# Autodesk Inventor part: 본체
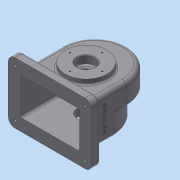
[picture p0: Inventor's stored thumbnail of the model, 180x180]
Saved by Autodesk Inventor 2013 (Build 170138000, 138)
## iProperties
Created: 2017-11
Part Number: 본체
Material: 일반
Document SubType Name: Modeling
Designer: Administrator
Density: 1 g/cm^3
Author: Administrator
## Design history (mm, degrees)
sketch "스케치1"
  geometry: L1 (-58, 0)-(-58, -80); L2 (-58, -80)-(58, -80); L3 (58, 0)-(58, -80); A1 r 58 centre (0, 0) between (58, 0) and (-58, 0); 1 further point
  constraints: 6 end point, 2 perpendicular, 2 point on circle, 2 tangent, 1 centre point, 1 coincident, 1 vertical
  dimensions: "d0" = 116 diameter of A1; "d2" = 80 distance from line of L3.start L2
extrude "돌출1" new body sketch "스케치1" distance "d3" = 38; taper "d4" = 0 deg
sketch "스케치2"
  geometry: L1 (-58, -80)-(58, -80) reference; L2 (58, -80)-(58, 0) reference; L3 (-58, -23)-(-58, -80); L4 (-58, -80)-(58, -80); L5 (58, -23)-(58, -80); A1 r 58 centre (0, 0) between (58, 0) and (-58, 0) reference; A2 r 58 centre (0, -23) between (58, -23) and (-58, -23); 2 further points
  constraints: 6 end point, 2 midpoint, 2 perpendicular, 2 point on circle, 2 tangent, 1 centre point, 1 coincident, 1 parallel, 1 vertical alignment
  dimensions: "d6" = 57 distance from line of L4 L5.start; "d8" = 58 radius of A2
extrude "돌출2" join sketch "스케치2" distance "d9" = 38; taper "d10" = 0 deg
feature "쉘1" dims "d11" = 5
sketch "스케치3"
  geometry: L1 (-58, -80)-(58, -80) reference; C1 r 37.5 at (0, -15); A1 r 58 centre (0, 0) between (58, 0) and (-58, 0) reference
  constraints: 1 centre point, 1 vertical alignment
  dimensions: "d12" = 75 diameter of C1; "d13" = 65 distance from line of L1 C1.centre
extrude "돌출3" join sketch "스케치3" distance "d14" = 9; taper "d15" = 0 deg
sketch "스케치4"
  geometry: L1 (-58, -80)-(58, -80) reference; C1 r 31 at (0, -15); 1 further point
  constraints: 1 centre point, 1 vertical alignment
  dimensions: "d16" = 62 diameter of C1; "d17" = 65 distance from line of L1 C1.centre
extrude "돌출4" join sketch "스케치4" distance "d18" = 10; taper "d19" = 0 deg
sketch "스케치5"
  geometry: C1 r 31 at (0, 0) reference; 1 further point
hole "구멍1" sketch "스케치5" at (0, 0) diameter "d20" = 32; stored, may be unused: countersink angle "d24" = 90 deg, drill point angle "d26" = 118 deg; dims "d21" = 6, "d22" = 4, "d23" = 2, "d25" = 8
chamfer "모따기1" distance "d29" = 1; stored, may be unused: second distance "d30" = 2, angle "d31" = 45 deg
fillet "모깎기2" dims "d32" = 3
fillet "모깎기3" dims "d33" = 3
node "작업 평면1"
sketch "스케치6"
  geometry: L1 (58, 38)-(-58, 38) reference; C1 r 6 at (0, 19); 1 further point
  constraints: 1 centre point, 1 vertical alignment
  dimensions: "d35" = 12 diameter of C1; "d47" = 19 distance from line of L1 C1.centre
extrude "돌출5" join sketch "스케치6" stored distance "d38" = 10; taper "d39" = 0 deg
sketch "스케치7"
  geometry: C1 r 6 at (0, 0) reference; 1 further point
hole "구멍2" sketch "스케치7" at (0, 0) diameter "d40" = 4.459; stored, may be unused: countersink angle "d44" = 90 deg, drill point angle "d46" = 118 deg; dims "d41" = 6, "d42" = 4, "d43" = 2, "d45" = 8
sketch "스케치8"
  geometry: L1 (116, 0)-(116, -76) reference; L2 (0, 0)-(116, 0) reference; L3 (0, 0)-(0, -76) reference; L4 (116, -76)-(0, -76) reference; L5 (-17, 17)-(133, 17); L6 (133, 17)-(133, -93); L7 (133, -93)-(-17, -93); L8 (-17, -93)-(-17, 17); 3 further points
  constraints: 8 end point, 2 midpoint, 2 parallel, 1 horizontal, 1 horizontal alignment, 1 perpendicular, 1 vertical alignment
  dimensions: "d48" = 110 distance of L5.end L6.end; "d50" = 150 distance of L6.end L7.end
extrude "돌출6" join sketch "스케치8" distance "d51" = 15; taper "d52" = 0 deg
fillet "모깎기4" dims "d53" = 12
sketch "스케치9"
  geometry: A1 r 12 centre (-5, 81) between (-5, 93) and (-17, 81) reference; 1 further point
hole "구멍3" sketch "스케치9" at (-5, 81) diameter "d54" = 5; stored, may be unused: countersink angle "d58" = 90 deg, drill point angle "d60" = 0 deg; dims "d55" = 6, "d56" = 12, "d57" = 5, "d59" = 8
sketch "스케치10"
  geometry: A1 r 12 centre (-5, -5) between (-17, -5) and (-5, -17) reference; A2 r 12 centre (121, -5) between (121, -17) and (133, -5) reference; A3 r 12 centre (121, 81) between (133, 81) and (121, 93) reference; 1 further point
hole "구멍4" sketch "스케치10" at (-5, -5), (121, -5), (121, 81) diameter "d61" = 5; stored, may be unused: countersink angle "d65" = 90 deg, drill point angle "d67" = 0 deg; dims "d62" = 6, "d63" = 12, "d64" = 5, "d66" = 8
sketch "스케치11"
  geometry: C1 r 31 at (0, 0) reference; 2 further points
  constraints: 1 vertical alignment
  dimensions: "d68" = 26 distance of C1.centre point (0, 26)
hole "구멍5" sketch "스케치11" at (0, 26) diameter "d69" = 2.459; stored, may be unused: countersink angle "d73" = 90 deg, drill point angle "d75" = 118 deg; dims "d70" = 6, "d71" = 12, "d72" = 5, "d74" = 8
sketch "스케치12"
  geometry: C1 r 37.5 at (0, 0) reference; 2 further points
  constraints: 1 vertical alignment
  dimensions: "d79" = 29 distance of C1.centre point (0, 29)
hole "구멍6" sketch "스케치12" at (0, 29) diameter "d80" = 2.459; stored, may be unused: countersink angle "d84" = 90 deg, drill point angle "d86" = 118 deg; dims "d81" = 6, "d82" = 12, "d83" = 5, "d85" = 8
fillet "모깎기6" dims "d91" = 8
fillet "모깎기7" dims "d92" = 3
fillet "모깎기8" dims "d93" = 3
sketch "스케치13"
  geometry: L1 (-13, -80)-(-25, -80) reference; L2 (-8, 0)-(-8, -62) reference; 2 further points
  constraints: 1 other
  dimensions: "d94" = 40 distance from line of L1 point (30, -40); "d95" = 38 distance from line of L2 point (30, -40)
feature "엠보싱1" sketch "스케치13" dims "d96" = 0.5, "d97" = 0
node "솔리드1"
pattern_circular "원형 패턴1" dims angle "d77" = 360 deg
pattern_circular "원형 패턴2" dims angle "d88" = 360 deg
other parameters: "d5" = 116, "d34" = 64
